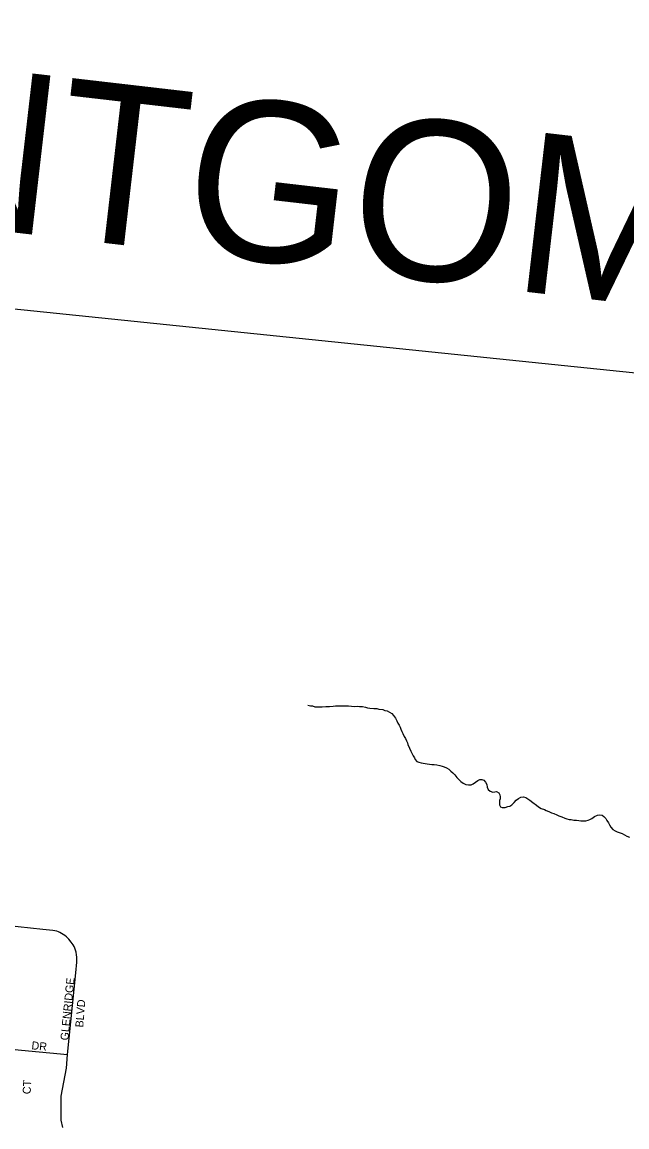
# Model space of a CAD drawing. Extents: x 0 to 1064, y 0 to 440.
# Drawn here: x 266.76 to 278.22, y 386.56 to 407.47 of the extents above; entities that cross this region are included whole.
import ezdxf

# ---------------------------------------------------------------- set-up
doc = ezdxf.new("R2010")
doc.units = 0
for name, color, linetype in [('GM_X_Adjacent_County_Text', 7, 'Continuous'), ('GM_X_County', 7, 'Continuous'), ('GM_X_Minor_River', 7, 'Continuous'), ('GM_X_Township', 7, 'Continuous'), ('GM_X_Township_Subdivision', 7, 'Continuous'), ('GM_X_Township_Subdivision_Text', 7, 'Continuous')]:
    doc.layers.add(name, color=color, linetype=linetype)

msp = doc.modelspace()

# ---------------------------------------------------------------- linework, layer by layer
at = {"layer": 'GM_X_County'}
msp.add_lwpolyline([(215.136, 407.282), (226.594, 406.09), (236.573, 405.067), (237.614, 404.96), (239.786, 404.737), (242.816, 404.427), (251.035, 403.584), (257.698, 402.932), (262.996, 402.414), (278.936, 400.777), (282.471, 400.414), (283.829, 400.275), (308.668, 397.643)], dxfattribs=at)
at = {"layer": 'GM_X_Minor_River'}
for points in [[(272.172, 394.542), (272.221, 394.528), (272.263, 394.527), (272.305, 394.514), (272.354, 394.513), (272.397, 394.512), (272.445, 394.511), (272.512, 394.515), (272.549, 394.52), (272.585, 394.519), (272.652, 394.524), (272.695, 394.529), (272.731, 394.528), (272.774, 394.527), (272.811, 394.532), (272.847, 394.531), (272.89, 394.53), (272.944, 394.529), (272.999, 394.521), (273.06, 394.52), (273.108, 394.524), (273.151, 394.517), (273.205, 394.516), (273.266, 394.502), (273.302, 394.495), (273.345, 394.488), (273.423, 394.48), (273.478, 394.479), (273.514, 394.466), (273.593, 394.458), (273.629, 394.444), (273.672, 394.437), (273.72, 394.412), (273.761, 394.386), (273.797, 394.349), (273.832, 394.299), (273.855, 394.244), (273.878, 394.201), (273.902, 394.164), (273.919, 394.127), (273.936, 394.09), (273.953, 394.047), (273.971, 394.004), (274, 393.948), (274.023, 393.911), (274.04, 393.868), (274.057, 393.831), (274.069, 393.795), (274.097, 393.727), (274.126, 393.672), (274.144, 393.635), (274.167, 393.585), (274.19, 393.548), (274.207, 393.511), (274.237, 393.474), (274.273, 393.461), (274.321, 393.448), (274.358, 393.447), (274.394, 393.44), (274.43, 393.433), (274.479, 393.425), (274.521, 393.418), (274.564, 393.417), (274.618, 393.41), (274.673, 393.402), (274.715, 393.389), (274.757, 393.376), (274.799, 393.357), (274.841, 393.331), (274.883, 393.294), (274.918, 393.262), (274.954, 393.225), (274.995, 393.175), (275.031, 393.138), (275.072, 393.1), (275.114, 393.069), (275.162, 393.043), (275.217, 393.036), (275.265, 393.035), (275.302, 393.052), (275.346, 393.087), (275.395, 393.117), (275.432, 393.134), (275.468, 393.133), (275.505, 393.12), (275.54, 393.082), (275.563, 393.039), (275.568, 392.991), (275.585, 392.948), (275.627, 392.916), (275.675, 392.897), (275.712, 392.902), (275.748, 392.907), (275.79, 392.882), (275.808, 392.845), (275.813, 392.808), (275.812, 392.771), (275.805, 392.735), (275.804, 392.693), (275.803, 392.656), (275.82, 392.619)], [(275.82, 392.619), (275.856, 392.606), (275.911, 392.605), (275.96, 392.622), (275.997, 392.633), (276.034, 392.656), (276.078, 392.698), (276.121, 392.745), (276.165, 392.775), (276.208, 392.804), (276.257, 392.809), (276.299, 392.796), (276.341, 392.77), (276.377, 392.745), (276.436, 392.701), (276.502, 392.651), (276.538, 392.619), (276.592, 392.588), (276.652, 392.568), (276.688, 392.549), (276.736, 392.529), (276.79, 392.504), (276.832, 392.49), (276.886, 392.465), (276.928, 392.445), (276.983, 392.426), (277.037, 392.406), (277.079, 392.393), (277.121, 392.38), (277.158, 392.379), (277.212, 392.365), (277.261, 392.364), (277.303, 392.357), (277.34, 392.356), (277.394, 392.355), (277.437, 392.354), (277.48, 392.365), (277.516, 392.376), (277.554, 392.399), (277.603, 392.435), (277.658, 392.458), (277.701, 392.469), (277.744, 392.461), (277.779, 392.436), (277.815, 392.399), (277.838, 392.362), (277.868, 392.318), (277.885, 392.275), (277.914, 392.232), (277.949, 392.189), (277.991, 392.163), (278.033, 392.144), (278.088, 392.124), (278.124, 392.111), (278.172, 392.086), (278.214, 392.066), (278.262, 392.041)]]:
    msp.add_lwpolyline(points, dxfattribs=at)
at = {"layer": 'GM_X_Township'}
msp.add_lwpolyline([(215.136, 407.282), (226.594, 406.09), (236.573, 405.067), (237.614, 404.96), (239.786, 404.737), (242.816, 404.427), (251.035, 403.584), (257.698, 402.932), (262.996, 402.414), (278.936, 400.777), (282.471, 400.414), (283.829, 400.275), (308.668, 397.643)], dxfattribs=at)
at = {"layer": 'GM_X_Township_Subdivision'}
for points in [[(267.534, 386.55), (267.502, 386.687), (267.502, 386.865), (267.502, 387.139), (267.599, 387.671), (267.623, 387.929), (267.777, 389.474), (267.798, 389.681), (267.799, 389.728), (267.797, 389.774), (267.792, 389.82), (267.783, 389.865), (267.771, 389.905), (267.758, 389.942), (267.744, 389.976), (267.727, 390.006), (267.69, 390.058), (267.644, 390.115), (267.602, 390.157), (267.572, 390.18), (267.539, 390.203), (267.477, 390.238), (267.448, 390.252), (267.42, 390.262), (267.381, 390.272), (267.341, 390.28), (267.154, 390.299), (265.982, 390.422)], [(265.412, 386.989), (265.507, 388.028), (265.517, 388.1), (265.534, 388.113), (265.568, 388.127), (265.592, 388.13), (265.65, 388.123), (266.751, 388.015), (267.623, 387.929)]]:
    msp.add_lwpolyline(points, dxfattribs=at)

# ---------------------------------------------------------------- texts
at = {"layer": 'GM_X_Adjacent_County_Text'}
msp.add_text('MONTGOMERY COUNTY', height=3.0303, rotation=353.3955, dxfattribs=at).set_placement((257.885, 404.499))
at = {"layer": 'GM_X_Township_Subdivision_Text'}
for s, rotation, p in [('GLENRIDGE', 84.2176, (267.635, 388.192)), ('BLVD', 85.483, (267.918, 388.438)), ('DR', 353.9946, (266.933, 388.031)), ('CT', 86.8107, (266.921, 387.176))]:
    msp.add_text(s, height=0.1515, rotation=rotation, dxfattribs=at).set_placement(p)

doc.saveas('drawing.dxf')
